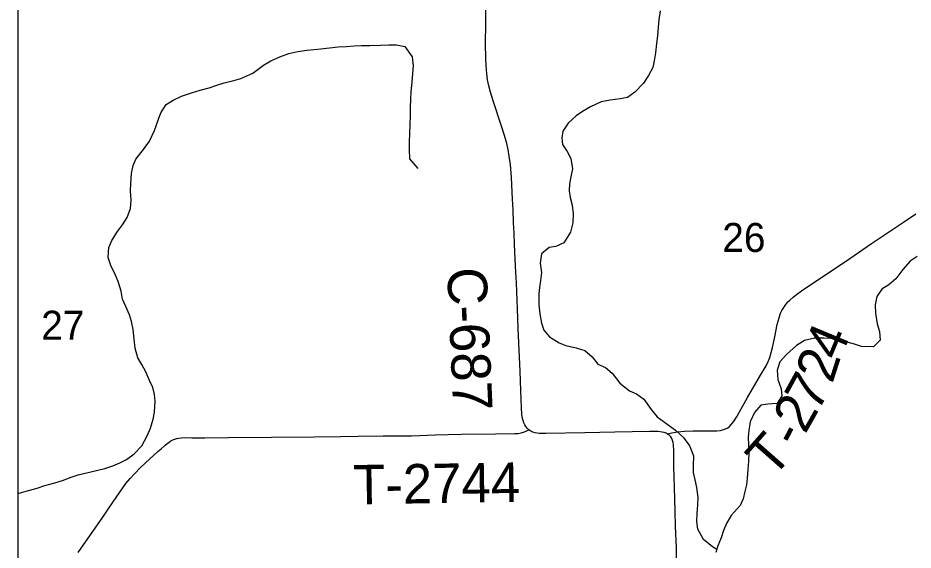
# Model space of a CAD drawing. Extents: x -7.5 to 53.5, y 0 to 22.
# Drawn here: x 2.1 to 3.39, y 18.461 to 19.229 of the extents above; entities that cross this region are included whole.
import ezdxf

# ---------------------------------------------------------------- set-up
doc = ezdxf.new("R2010")
doc.units = 0
for name, color, linetype in [('GM_X_Corporation', 7, 'Continuous'), ('GM_X_County_Road', 7, 'Continuous'), ('GM_X_County_Road_Text', 7, 'Continuous'), ('GM_X_Minor_River', 7, 'Continuous'), ('GM_X_Section_Text', 7, 'Continuous'), ('GM_X_Township_Road', 7, 'Continuous'), ('GM_X_Township_Road_Text', 7, 'Continuous'), ('SH_Data', 7, 'Continuous')]:
    doc.layers.add(name, color=color, linetype=linetype)

msp = doc.modelspace()

# ---------------------------------------------------------------- linework, layer by layer
at = {"layer": 'GM_X_Corporation'}
msp.add_lwpolyline([(4.6087, 14.5302), (4.6021, 15.6139), (4.594, 15.8096), (4.5873, 16.3533), (4.5872, 16.3635), (4.5826, 16.8462), (4.5822, 16.8992), (4.577, 17.1178), (4.5749, 17.2575), (4.5771, 17.6201), (4.5718, 18.1276), (4.5696, 18.2604), (4.5565, 19.1354), (5.0411, 19.1401), (6.0424, 19.1527), (6.0433, 19.1527), (6.5522, 19.1561), (7.544, 19.1455), (8.414, 19.1709), (8.5159, 19.1718), (8.9, 19.1887), (8.9, 20.9), (2.1, 20.9), (2.1, 14.1)], dxfattribs=at)
at = {"layer": 'GM_X_County_Road'}
for points in [[(2.8367, 18.6349), (2.8344, 18.6371), (2.8323, 18.6396), (2.8306, 18.6423), (2.8292, 18.6452), (2.8281, 18.6482), (2.8273, 18.6513), (2.8263, 18.6575), (2.8257, 18.6669), (2.8248, 18.6918), (2.8239, 18.7197), (2.8222, 18.7601), (2.8213, 18.7818), (2.82, 18.8096), (2.8185, 18.8468), (2.8177, 18.8623), (2.8167, 18.8809), (2.8157, 18.9026), (2.8151, 18.9181), (2.8145, 18.9336), (2.8137, 18.9521), (2.813, 18.9676), (2.8113, 18.9987), (2.8099, 19.0177), (2.8083, 19.0297), (2.8067, 19.0394), (2.8049, 19.0478), (2.8013, 19.0593), (2.7967, 19.0744), (2.7849, 19.1093), (2.7812, 19.1222), (2.779, 19.131), (2.777, 19.14), (2.7757, 19.1488), (2.7749, 19.1603), (2.7743, 19.1708), (2.7741, 19.1924), (2.7747, 19.2206), (2.7746, 19.3169)], [(3.0361, 18.6293), (3.0344, 18.6302), (3.0317, 18.6312), (3.0288, 18.6318), (3.0226, 18.6324), (3.0102, 18.6324), (2.9605, 18.6315), (2.917, 18.6306), (2.8611, 18.6295), (2.8516, 18.6297), (2.8485, 18.6301), (2.8454, 18.6307), (2.8423, 18.6318), (2.8394, 18.6331), (2.8367, 18.6349)], [(3.0531, 18.3609), (3.0527, 18.3697), (3.0516, 18.387), (3.0502, 18.4243), (3.0495, 18.446), (3.0491, 18.4647), (3.0481, 18.4957), (3.0475, 18.5174), (3.0463, 18.5516), (3.0457, 18.5827), (3.0453, 18.6044), (3.0449, 18.6137), (3.0444, 18.6167), (3.0437, 18.6196), (3.0427, 18.6224), (3.0412, 18.6249), (3.0393, 18.627), (3.037, 18.6288), (3.0361, 18.6293)]]:
    msp.add_lwpolyline(points, dxfattribs=at)
at = {"layer": 'GM_X_Minor_River'}
for points in [[(3.0258, 19.2394), (3.0238, 19.2265), (3.0231, 19.2159), (3.0219, 19.2033), (3.0204, 19.1923), (3.0192, 19.179), (3.0173, 19.1673), (3.015, 19.1578), (3.0089, 19.146), (3.0017, 19.135), (2.9892, 19.1221), (2.9789, 19.1145), (2.9683, 19.1122), (2.9535, 19.1103), (2.9406, 19.1081), (2.9254, 19.1009), (2.914, 19.094), (2.9045, 19.088), (2.8931, 19.0773), (2.8855, 19.0659), (2.884, 19.0561), (2.8851, 19.0466), (2.8915, 19.0363), (2.8968, 19.0264), (2.8995, 19.0116), (2.8972, 18.9999), (2.8949, 18.99), (2.8945, 18.9797), (2.896, 18.9702), (2.8987, 18.9589), (2.9005, 18.9463), (2.8998, 18.9334), (2.8967, 18.9201), (2.8868, 18.9049), (2.8754, 18.8996), (2.8659, 18.8981), (2.8545, 18.889), (2.8526, 18.8753), (2.8545, 18.8617), (2.8534, 18.8503), (2.8518, 18.8408), (2.8511, 18.8305), (2.851, 18.8153), (2.8525, 18.8024), (2.8548, 18.7888), (2.8582, 18.7789), (2.8665, 18.769), (2.8802, 18.7603), (2.8897, 18.7565), (2.9045, 18.7534), (2.917, 18.7492), (2.9276, 18.7401), (2.936, 18.7295), (2.947, 18.7249), (2.9568, 18.7169), (2.9678, 18.7025), (2.9815, 18.6911), (2.9917, 18.6869), (3.002, 18.6793), (3.0129, 18.6645), (3.0213, 18.6535), (3.0477, 18.6347)], [(2.1, 18.5434), (2.1018, 18.5438), (2.1117, 18.5465), (2.1276, 18.5506), (2.139, 18.5548), (2.1534, 18.5586), (2.1641, 18.562), (2.177, 18.5665), (2.1869, 18.57), (2.2153, 18.5768), (2.2252, 18.5794), (2.2366, 18.5828), (2.2469, 18.5874), (2.2567, 18.5923), (2.2674, 18.6003), (2.2784, 18.6121), (2.2864, 18.6265), (2.2913, 18.6375), (2.2951, 18.6504), (2.297, 18.6603), (2.2978, 18.6762), (2.2971, 18.6861), (2.2944, 18.696), (2.2899, 18.7062), (2.2842, 18.7184), (2.2785, 18.7294), (2.2728, 18.7389), (2.2691, 18.7526), (2.2676, 18.7659), (2.2661, 18.7799), (2.2638, 18.7913), (2.2608, 18.8008), (2.2555, 18.813), (2.2509, 18.8232), (2.2487, 18.835), (2.2445, 18.849), (2.2392, 18.8612), (2.2343, 18.8707), (2.2301, 18.8836), (2.2309, 18.898), (2.2355, 18.9079), (2.2438, 18.9212), (2.2507, 18.9307), (2.2575, 18.9413), (2.2625, 18.9542), (2.2632, 18.9664), (2.2625, 18.9797), (2.2629, 18.9899), (2.2637, 19.0047), (2.266, 19.0161), (2.2701, 19.0256), (2.2812, 19.0393), (2.2895, 19.0514), (2.2968, 19.0666), (2.3025, 19.0829), (2.3059, 19.0924), (2.3139, 19.1042), (2.3238, 19.1103), (2.3359, 19.1163), (2.3503, 19.1213), (2.3625, 19.1247), (2.3758, 19.1281), (2.3868, 19.1319), (2.3974, 19.1353), (2.4111, 19.1387), (2.4213, 19.1417), (2.4384, 19.1493), (2.454, 19.1611), (2.4646, 19.1672), (2.4776, 19.1732), (2.4905, 19.1778), (2.5034, 19.1808), (2.5163, 19.1827), (2.5368, 19.1846), (2.5493, 19.1861), (2.5615, 19.1872), (2.5736, 19.188), (2.5846, 19.1887), (2.5952, 19.1891), (2.6074, 19.1891), (2.6226, 19.1899), (2.6347, 19.1902), (2.6457, 19.1902), (2.6575, 19.1879), (2.6681, 19.1731), (2.6696, 19.1602), (2.6688, 19.1488), (2.6677, 19.1367), (2.6665, 19.1222), (2.6658, 19.1124), (2.6654, 19.0995), (2.6654, 19.0877), (2.665, 19.0752), (2.6646, 19.0623), (2.6638, 19.0497), (2.6638, 19.0391), (2.6645, 19.0258), (2.6767, 19.0117)], [(3.3964, 18.8849), (3.3862, 18.8781), (3.3756, 18.8663), (3.3655, 18.8526), (3.3553, 18.8442), (3.3454, 18.8377), (3.3383, 18.8274)], [(3.3383, 18.8274), (3.3357, 18.8153), (3.3361, 18.8031), (3.3388, 18.7879), (3.3419, 18.777), (3.3431, 18.7641), (3.3333, 18.7549), (3.3162, 18.7552), (3.306, 18.7586), (3.2954, 18.7616), (3.2844, 18.7642), (3.2715, 18.7668), (3.2616, 18.7672), (3.2483, 18.7671), (3.234, 18.7636), (3.2222, 18.7568), (3.2079, 18.7438), (3.1981, 18.7331), (3.1944, 18.721), (3.1955, 18.7077), (3.2002, 18.6941), (3.201, 18.6842), (3.1942, 18.6728), (3.1809, 18.672), (3.1711, 18.6704), (3.1616, 18.6598), (3.1556, 18.6465), (3.1534, 18.6339), (3.1527, 18.6244), (3.1531, 18.6131), (3.1535, 18.6032), (3.1532, 18.5891), (3.1521, 18.5778), (3.1511, 18.5652), (3.15, 18.5557), (3.1477, 18.5459), (3.1455, 18.5356), (3.141, 18.5257), (3.1282, 18.5113), (3.1218, 18.501), (3.1173, 18.4896), (3.1135, 18.4793), (3.109, 18.4675), (3.106, 18.458)], [(3.1074, 18.4623), (3.1011, 18.4664), (3.0881, 18.4766), (3.0801, 18.4917), (3.0786, 18.5027), (3.0789, 18.5141), (3.0803, 18.527), (3.0807, 18.5373), (3.0787, 18.552), (3.076, 18.5627), (3.0737, 18.5733), (3.074, 18.5839), (3.0744, 18.5972), (3.0682, 18.6127), (3.0606, 18.6229), (3.0477, 18.6347)]]:
    msp.add_lwpolyline(points, dxfattribs=at)
at = {"layer": 'GM_X_Township_Road'}
for points in [[(3.0361, 18.6293), (3.0426, 18.6307), (3.0507, 18.6321), (3.0609, 18.633), (3.0732, 18.6334), (3.0856, 18.6334), (3.0982, 18.6336), (3.1074, 18.6337), (3.1126, 18.6342), (3.1171, 18.6353), (3.1201, 18.6363), (3.1231, 18.6377), (3.1259, 18.6398), (3.1287, 18.643), (3.1315, 18.6464), (3.1366, 18.6545), (3.14, 18.6607), (3.1519, 18.6817), (3.1705, 18.7136), (3.1784, 18.7275), (3.182, 18.7347), (3.184, 18.7395), (3.1855, 18.7446), (3.1877, 18.7538), (3.1909, 18.769), (3.1946, 18.7871), (3.1972, 18.7965), (3.1994, 18.803), (3.2013, 18.8071), (3.2039, 18.8116), (3.2067, 18.8158), (3.21, 18.8194), (3.2127, 18.8222), (3.2174, 18.8261), (3.2222, 18.8301), (3.2294, 18.8353), (3.2504, 18.8495), (3.2684, 18.8614), (3.2992, 18.8823), (3.3305, 18.9036), (3.3605, 18.9241), (3.3763, 18.9343), (3.3942, 18.9463)], [(2.187, 18.458), (2.2047, 18.4835), (2.2222, 18.5091), (2.2309, 18.5219), (2.2467, 18.545), (2.2558, 18.5575), (2.2617, 18.5647), (2.2679, 18.5717), (2.2767, 18.5805), (2.2904, 18.5931), (2.3017, 18.6035), (2.3063, 18.6074), (2.3106, 18.6115), (2.3129, 18.6135), (2.3178, 18.6173), (2.3204, 18.619), (2.3232, 18.6204), (2.3261, 18.6215), (2.329, 18.6224), (2.332, 18.6231), (2.3351, 18.6235), (2.3413, 18.6239), (2.3506, 18.6236), (2.3693, 18.6235), (2.4034, 18.624), (2.5276, 18.6249), (2.5648, 18.6254), (2.5904, 18.6256), (2.6263, 18.6262), (2.6673, 18.6264), (2.7014, 18.6276), (2.7387, 18.6286), (2.7883, 18.6293), (2.8163, 18.6297), (2.821, 18.6298), (2.8256, 18.6304), (2.8304, 18.632), (2.8353, 18.6343), (2.8367, 18.6349)]]:
    msp.add_lwpolyline(points, dxfattribs=at)
at = {"layer": 'SH_Data'}
msp.add_line((2.1, 20.9), (2.1, 14.1), dxfattribs=at)

# ---------------------------------------------------------------- texts
at = {"layer": 'GM_X_County_Road_Text'}
msp.add_text('C-687', height=0.05682, rotation=272.4771, dxfattribs=at).set_placement((2.7186, 18.8682))
at = {"layer": 'GM_X_Section_Text'}
for s, p in [('26', (3.1153, 18.8915)), ('27', (2.1336, 18.7649))]:
    msp.add_text(s, height=0.04186, rotation=0, dxfattribs=at).set_placement(p)
at = {"layer": 'GM_X_Township_Road_Text'}
for s, height, rotation, p in [('4', 0.0568, 67.3945, (3.2842, 18.7326)), ('2', 0.0568, 72.216, (3.2739, 18.7005)), ('7', 0.0568, 61.3091, (3.2525, 18.6589)), ('2', 0.0568, 60.5385, (3.2348, 18.6277)), ('T', 0.0568, 48.6843, (3.1878, 18.5635)), ('-', 0.0568, 62.2947, (3.2242, 18.6075)), ('T-2744', 0.05682, 0.9354, (2.5836, 18.5273))]:
    msp.add_text(s, height=height, rotation=rotation, dxfattribs=at).set_placement(p)

doc.saveas('drawing.dxf')
